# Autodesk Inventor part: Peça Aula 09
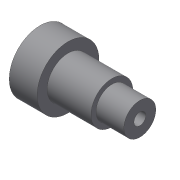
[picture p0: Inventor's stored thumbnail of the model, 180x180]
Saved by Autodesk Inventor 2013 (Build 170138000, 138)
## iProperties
Created: 2012-12
Part Number: Peça Aula 09
Material: Genérico
Document SubType Name: Modeling
Designer: Daniel Severino
Density: 1 g/cm^3
Author: Daniel Severino
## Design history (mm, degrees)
sketch "Esboço1"
  geometry: L1 (0, 0)-(100, 0); L2 (100, 0)-(100, 10); L3 (100, 10)-(72, 10); L4 (72, 10)-(72, 15); L5 (72, 15)-(28, 15); L6 (28, 15)-(28, 25); L7 (28, 25)-(0, 25); L8 (0, 25)-(0, 0); L9 (0, -6)-(100, -6)
  constraints: 18 end point, 2 vertical, 1 horizontal
  dimensions: "d0" = 100 distance of L1.start L1.end; "d1" = 10 distance of L1.end L2.end; "d2" = 25 distance of L7.end L1.start; "d4" = 15 distance between parallel lines of L1 L5; "d5" = 28 distance of L6.end L7.end; "d9" = 28 distance of L2.end L3.end; "d10" = 6 distance between parallel lines of L9 L1
revolve "Revolução1" sketch "Esboço1" stored, may be unused: angle "d8" = 180 deg
sketch "Esboço2"
  geometry: C1 r 12.5 at (0, 0); 2 further points
  constraints: 1 centre point, 1 coincident, 1 vertical alignment
  dimensions: "d11" = 25 diameter of C1
extrude "Extrusão1" cut sketch "Esboço2" distance "d13" = 12; taper "d14" = 0 deg
node "Sólido1"
